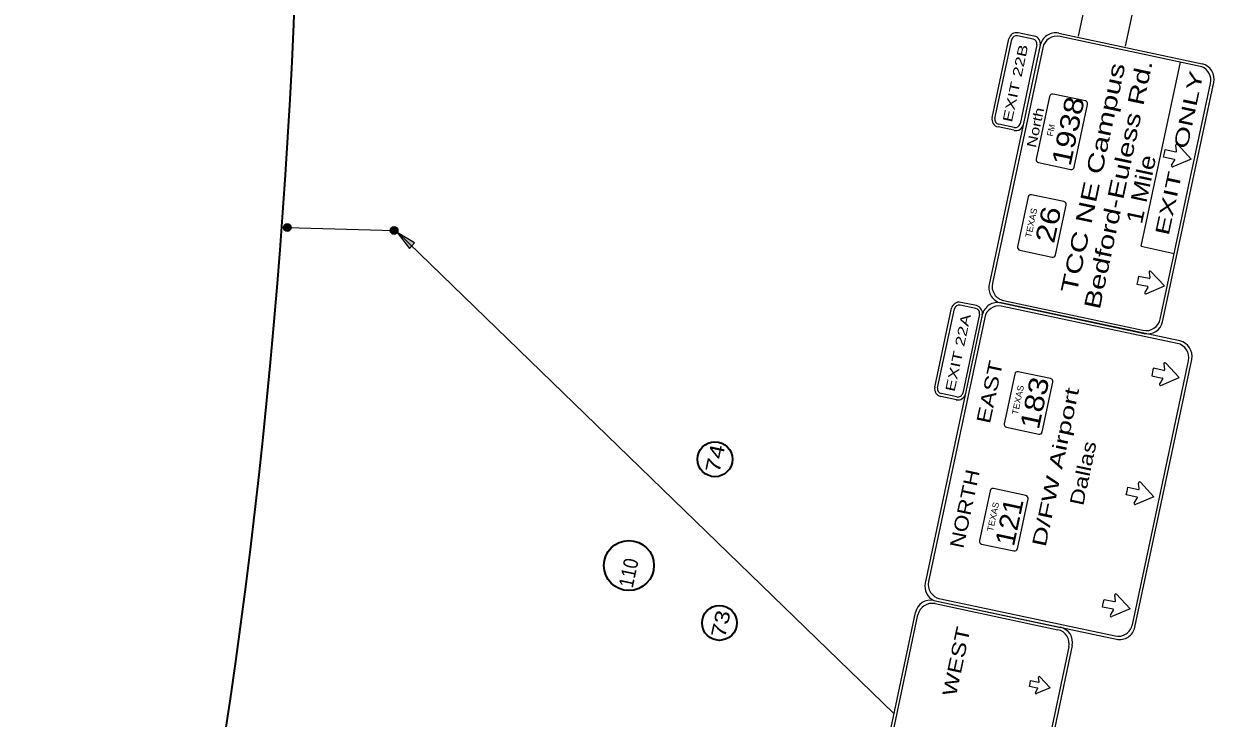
# Model space of a CAD drawing. Extents: x 2363411 to 2369702, y 6977197 to 6988655.
# Drawn here: x 2366110 to 2367261, y 6984077 to 6984748 of the extents above; entities that cross this region are included whole.
import ezdxf
from ezdxf.enums import TextEntityAlignment as Align

# ---------------------------------------------------------------- set-up
doc = ezdxf.new("R2010")
doc.units = 0
doc.header["$LTSCALE"] = 5.6
for name, color, linetype, lineweight in [('1', 7, 'Continuous', 25), ('17', 7, 'Continuous', 35), ('37', 7, 'Continuous', 13)]:
    doc.layers.add(name, color=color, linetype=linetype, lineweight=lineweight)

msp = doc.modelspace()

# ---------------------------------------------------------------- hatches: boundary and pattern name
at = {"layer": '1'}
for points in [[(2366366.647, 6984554.422, 1), (2366363.378, 6984547.712, 1)], [(2366469.912, 6984551.533, 1), (2366466.643, 6984544.824, 1)], [(2366471.082, 6984546.205), (2366483.256, 6984530.933), (2366487.97, 6984536.384)]]:
    msp.add_hatch(color=256, dxfattribs=at).paths.add_polyline_path(points)

# ---------------------------------------------------------------- linework, layer by layer
for p, q in [((2367138.659, 6984779.414), (2367129.448, 6984736.012)), ((2367184.046, 6984769.781), (2367174.834, 6984726.38)), ((2367085.868, 6984733.305), (2367070.751, 6984736.519)), ((2367086.453, 6984736.053), (2367071.337, 6984739.266)), ((2367110.621, 6984738.909), (2367249.302, 6984709.279)), ((2367248.837, 6984706.487), (2367111.875, 6984735.752)), ((2367092.767, 6984727.341), (2367043.331, 6984495.966)), ((2367046.219, 6984657.188), (2367062.442, 6984733.492)), ((2367095.133, 6984724.912), (2367046.484, 6984497.216)), ((2367048.968, 6984656.603), (2367065.189, 6984732.906)), ((2367089.48, 6984727.744), (2367073.249, 6984651.441)), ((2367190.312, 6984532.928), (2367228.339, 6984710.867)), ((2367208.74, 6984462.547), (2367257.429, 6984690.426)), ((2367211.039, 6984459.818), (2367260.475, 6984691.193)), ((2367101.799, 6984677.893), (2367088.902, 6984617.213)), ((2367136.372, 6984673.414), (2367105.14, 6984680.055)), ((2367125.636, 6984609.399), (2367138.533, 6984670.08)), ((2367067.103, 6984645.081), (2367051.995, 6984648.294)), ((2367067.69, 6984647.83), (2367052.579, 6984651.042)), ((2367213.604, 6984626.516), (2367223.763, 6984624.346)), ((2367224.582, 6984625.102), (2367223.811, 6984630.586)), ((2367091.065, 6984613.879), (2367122.296, 6984607.236)), ((2367219.688, 6984611.234), (2367222.623, 6984615.949)), ((2367081.118, 6984580.623), (2367070.876, 6984532.471)), ((2367115.69, 6984576.151), (2367084.459, 6984582.794)), ((2367107.61, 6984524.659), (2367117.852, 6984572.81)), ((2366365.012, 6984551.067), (2366468.277, 6984548.179)), ((2367073.047, 6984529.132), (2367104.277, 6984522.495)), ((2367190.312, 6984532.928), (2367222.317, 6984526.09)), ((2367197.915, 6984507.857), (2367198.686, 6984502.373)), ((2367186.131, 6984496.397), (2367196.293, 6984494.229)), ((2367196.727, 6984493.22), (2367193.792, 6984488.505)), ((2366990.767, 6984396.652), (2367006.998, 6984472.948)), ((2366993.515, 6984396.066), (2367009.737, 6984472.369)), ((2367030.417, 6984472.755), (2367015.307, 6984475.967)), ((2367031.004, 6984475.509), (2367015.893, 6984478.722)), ((2367227.663, 6984441.357), (2367054.898, 6984478.099)), ((2367054.898, 6984478.099), (2367193.245, 6984448.546)), ((2367225.242, 6984438.994), (2367055.105, 6984475.166)), ((2367057.334, 6984480.469), (2367191.995, 6984451.698)), ((2367036.777, 6984466.612), (2366981.625, 6984207.244)), ((2367039.139, 6984464.209), (2366984.841, 6984208.865)), ((2367034.021, 6984467.2), (2367017.798, 6984390.896)), ((2367181.781, 6984166.964), (2367236.077, 6984422.314)), ((2367184.143, 6984164.544), (2367239.219, 6984423.555)), ((2367212.21, 6984412.935), (2367212.186, 6984412.928)), ((2367212.236, 6984419.177), (2367213.003, 6984413.701)), ((2367068.229, 6984409.399), (2367057.993, 6984361.247)), ((2367102.8, 6984404.927), (2367071.57, 6984411.569)), ((2367094.729, 6984353.434), (2367104.963, 6984401.586)), ((2367211.055, 6984404.528), (2367208.123, 6984399.82)), ((2367012.246, 6984387.278), (2366997.128, 6984390.498)), ((2367011.66, 6984384.538), (2366996.55, 6984387.75)), ((2367060.156, 6984357.907), (2367091.387, 6984351.264)), ((2367078.783, 6984291.969), (2367047.551, 6984298.612)), ((2367177.528, 6984299.87), (2367187.689, 6984297.703)), ((2367188.499, 6984298.473), (2367187.734, 6984303.95)), ((2367044.212, 6984296.441), (2367033.969, 6984248.29)), ((2367070.704, 6984240.476), (2367080.946, 6984288.627)), ((2367183.619, 6984284.601), (2367186.551, 6984289.308)), ((2367036.139, 6984244.949), (2367067.369, 6984238.313)), ((2367165.459, 6984190.121), (2367164.693, 6984195.597)), ((2366990.007, 6984190.505), (2367166.348, 6984153.003)), ((2366990.007, 6984190.505), (2367112.427, 6984164.467)), ((2366991.262, 6984187.372), (2367109.633, 6984162.194)), ((2366996.484, 6984191.993), (2367165.099, 6984156.143)), ((2367154.487, 6984191.517), (2367164.649, 6984189.35)), ((2366937.872, 6984017.444), (2366972.227, 6984178.958)), ((2366941.013, 6984018.692), (2366974.591, 6984176.538)), ((2367160.579, 6984176.248), (2367163.511, 6984180.955)), ((2367120.468, 6984145.521), (2367086.899, 6983987.669)), ((2367123.601, 6984146.769), (2367089.253, 6983985.25)), ((2367091.704, 6984111.924), (2367091.125, 6984116.022)), ((2367083.481, 6984112.961), (2367091.093, 6984111.353)), ((2367088.043, 6984101.516), (2367090.234, 6984105.051))]:
    msp.add_line(p, q, dxfattribs=at)
at = {"layer": '1', "lineweight": 13}
msp.add_line((2366951.401, 6984081.046), (2366471.632, 6984546.544), dxfattribs=at)
at = {"layer": '1'}
for points in [[(2367225.591, 6984631.376), (2367238.622, 6984617.302), (2367220.991, 6984609.794)], [(2367222.189, 6984616.958), (2367212.027, 6984619.126), (2367212.822, 6984622.817), (2367213.604, 6984626.516)], [(2367195.095, 6984487.065), (2367212.726, 6984494.573), (2367199.695, 6984508.647)], [(2367197.867, 6984501.617), (2367187.708, 6984503.787), (2367186.926, 6984500.088), (2367186.131, 6984496.397)], [(2367212.186, 6984412.928), (2367202.024, 6984415.088), (2367201.241, 6984411.389), (2367200.457, 6984407.698), (2367210.619, 6984405.538)], [(2367209.428, 6984398.38), (2367227.053, 6984405.898), (2367214.016, 6984419.96)], [(2367186.114, 6984290.319), (2367175.953, 6984292.478), (2367176.744, 6984296.17), (2367177.528, 6984299.87)], [(2367189.512, 6984304.742), (2367202.549, 6984290.68), (2367184.923, 6984283.154)], [(2367166.471, 6984196.388), (2367179.508, 6984182.327), (2367161.883, 6984174.802)], [(2367163.074, 6984181.966), (2367152.913, 6984184.126), (2367153.703, 6984187.817), (2367154.487, 6984191.517)], [(2367092.451, 6984116.614), (2367102.224, 6984106.083), (2367089.01, 6984100.431)], [(2367089.911, 6984105.805), (2367082.29, 6984107.42), (2367082.883, 6984110.191), (2367083.481, 6984112.961)]]:
    msp.add_lwpolyline(points, dxfattribs=at)
msp.add_lwpolyline([(2366471.082, 6984546.205), (2366483.256, 6984530.933), (2366487.97, 6984536.384)], close=True, dxfattribs=at)
for centre in [(2366365.012, 6984551.067), (2366468.278, 6984548.179)]:
    msp.add_circle(centre, 3.732, dxfattribs=at)
at = {"layer": '1', "lineweight": 35}
msp.add_arc((2359877.328, 6985028.058), 6500, 337.9611, 358.49155, dxfattribs=at)
at = {"layer": '1'}
for centre, radius, start, end in [((2367069.779, 6984731.93), 7.501, 77.99433, 167.99433), ((2367069.779, 6984731.93), 4.688, 77.99433, 167.99433), ((2367085.43, 6984728.901), 7.501, 347.99433, 77.99433), ((2367107.483, 6984724.196), 15.049, 77.93925, 169.35675), ((2367108.929, 6984721.964), 14.108, 77.93925, 167.93925), ((2367084.892, 6984728.716), 4.688, 347.99433, 77.99433), ((2367243.631, 6984693.374), 14.108, 347.93925, 68.3439), ((2367245.824, 6984694.637), 15.049, 346.76968, 76.63979), ((2367104.551, 6984677.305), 2.813, 77.99516, 167.99516), ((2367135.785, 6984670.663), 2.813, 347.99516, 77.99516), ((2367053.553, 6984655.63), 7.501, 167.99433, 257.99433), ((2367053.553, 6984655.63), 4.688, 167.99433, 257.99433), ((2367069.135, 6984652.316), 7.501, 257.99433, 347.99433), ((2367068.666, 6984652.416), 4.688, 257.99433, 347.99433), ((2367224.831, 6984630.715), 1.012, 42.67771, 188.05885), ((2367223.928, 6984625.009), 0.675, 257.93922, 7.92232), ((2367091.646, 6984616.629), 2.813, 167.99516, 257.99516), ((2367122.88, 6984609.987), 2.813, 257.99516, 347.99516), ((2367220.558, 6984610.718), 1.012, 147.81958, 293.20072), ((2367222.066, 6984616.295), 0.675, 327.95611, 77.93922), ((2367083.867, 6984580.044), 2.813, 77.99516, 167.99516), ((2367115.102, 6984573.402), 2.813, 347.99516, 77.99516), ((2367073.626, 6984531.881), 2.813, 167.99516, 257.99516), ((2367104.86, 6984525.24), 2.813, 257.99516, 347.99516), ((2367198.936, 6984507.986), 1.012, 42.67771, 188.05885), ((2367058.047, 6984492.821), 15.049, 167.93925, 257.93925), ((2367060.28, 6984494.268), 14.108, 167.93925, 257.93925), ((2367196.171, 6984493.566), 0.675, 327.95611, 77.93922), ((2367198.033, 6984502.28), 0.675, 257.93922, 7.92232), ((2367194.663, 6984487.989), 1.012, 147.81958, 293.20072), ((2367014.327, 6984471.386), 7.501, 77.99516, 167.99516), ((2367014.327, 6984471.386), 4.688, 77.99516, 167.99516), ((2367029.44, 6984468.172), 4.688, 347.99516, 77.99516), ((2367029.44, 6984468.172), 7.501, 347.99516, 77.99516), ((2367051.448, 6984463.497), 15.001, 76.71396, 167.99516), ((2367052.894, 6984461.281), 14.063, 80.95422, 167.99516), ((2367194.942, 6984465.495), 14.108, 257.93925, 347.93925), ((2367196.389, 6984463.262), 15.049, 257.93925, 346.76968), ((2367222.32, 6984425.231), 14.063, 347.99516, 77.99516), ((2367224.544, 6984426.675), 15.001, 347.99516, 77.99516), ((2367212.35, 6984413.595), 0.675, 257.99516, 7.97826), ((2367213.248, 6984419.302), 1.012, 42.73365, 188.11479), ((2367070.98, 6984408.819), 2.813, 77.99516, 167.99516), ((2367102.215, 6984402.177), 2.813, 347.99516, 77.99516), ((2367210.497, 6984404.879), 0.675, 328.01205, 77.99516), ((2366998.102, 6984395.085), 7.501, 167.99516, 257.99516), ((2366998.102, 6984395.085), 4.688, 167.99516, 257.99516), ((2367013.215, 6984391.871), 7.501, 257.99516, 347.99516), ((2367013.215, 6984391.871), 4.688, 257.99516, 347.99516), ((2367208.995, 6984399.301), 1.012, 147.87552, 293.25666), ((2367060.739, 6984360.656), 2.813, 167.99516, 257.99516), ((2367091.973, 6984354.015), 2.813, 257.99516, 347.99516), ((2367046.961, 6984295.862), 2.813, 77.99516, 167.99516), ((2367187.849, 6984298.374), 0.675, 257.99516, 7.97826), ((2367188.746, 6984304.081), 1.012, 42.73365, 188.11479), ((2367078.195, 6984289.22), 2.813, 347.99516, 77.99516), ((2367185.996, 6984289.658), 0.675, 328.01205, 77.99516), ((2367184.493, 6984284.08), 1.012, 147.87552, 293.25666), ((2367036.719, 6984247.699), 2.813, 167.99516, 257.99516), ((2367067.953, 6984241.058), 2.813, 257.99516, 347.99516), ((2366996.293, 6984204.122), 15.001, 167.99516, 245.22121), ((2366998.595, 6984205.933), 14.063, 167.99516, 257.99516), ((2367165.706, 6984195.728), 1.012, 42.73365, 188.11479), ((2366986.896, 6984175.838), 15.001, 77.99525, 167.99525), ((2366988.34, 6984173.614), 14.063, 77.99525, 167.99525), ((2367164.808, 6984190.021), 0.675, 257.99516, 7.97826), ((2367161.453, 6984175.727), 1.012, 147.87552, 293.25666), ((2367162.955, 6984181.305), 0.675, 328.01205, 77.99516), ((2367106.712, 6984148.443), 14.063, 347.99525, 77.99525), ((2367108.936, 6984149.888), 15.001, 347.99525, 77.99525), ((2367168.023, 6984169.891), 14.063, 257.99516, 347.99516), ((2367169.467, 6984167.667), 15.001, 257.99516, 347.99516), ((2367091.883, 6984116.124), 0.759, 42.73196, 188.11309), ((2367089.82, 6984105.307), 0.506, 328.01036, 77.99346), ((2367091.21, 6984111.843), 0.506, 257.99346, 7.97657), ((2367088.693, 6984101.123), 0.759, 147.87383, 293.25497)]:
    msp.add_arc(centre, radius, start, end, dxfattribs=at)
at = {"layer": '17'}
for centre, radius in [((2366778.372, 6984326.964), 16.828), ((2366695.25, 6984224.179), 24.19), ((2366782.677, 6984168.728), 16.828)]:
    msp.add_circle(centre, radius, dxfattribs=at)
at = {"layer": '37'}
msp.add_line((2367088.416, 6984660.876), (2367087.523, 6984659.087), dxfattribs=at)

# ---------------------------------------------------------------- texts
at = {"layer": '1'}
for s, height, rotation, width, p in [('EXIT 22B', 9.188, 77.994, 1.45, (2367073.24, 6984689.621)), ('TCC NE Campus', 15.68, 77.939, 1.4, (2367151.437, 6984597.449)), ('Bedford-Euless Rd.', 15.68, 77.939, 1.35, (2367175.843, 6984591.161)), ('EXIT   ONLY', 13.5, 77.939, 1.55, (2367233.743, 6984621.698)), ('North', 9.188, 77.994, 1.3, (2367092.566, 6984646.777)), ('1 Mile', 15.68, 77.939, 1.2, (2367197.929, 6984586.441)), ('EXIT 22A', 9.188, 77.995, 1.45, (2367017.786, 6984429.083)), ('EAST', 13.5, 77.995, 1.3, (2367050.45, 6984390.673)), ('D/FW Airport', 13.5, 77.995, 1.5, (2367114.122, 6984318.045)), ('Dallas', 13.5, 77.995, 1.25, (2367140.761, 6984312.101)), ('NORTH', 13.5, 77.995, 1.2, (2367026.42, 6984277.709)), ('WEST', 13.5, 77.995, 1.3, (2367018.314, 6984130.096))]:
    msp.add_text(s, height=height, rotation=rotation, dxfattribs=dict(at, width=width)).set_placement(p, align=Align.CENTER)
for s, height, width, p in [('1938', 18.75, 1.2, (2367121.899, 6984609.67)), ('TEXAS', 6, 1.1, (2367083.99, 6984540.763)), ('26', 18.75, 1.25, (2367106, 6984534.893)), ('183', 18.75, 1.2, (2367091.244, 6984354.877)), ('TEXAS', 6, 1.1, (2367071.101, 6984369.537)), ('121', 18.75, 1.1, (2367067.227, 6984241.92)), ('TEXAS', 6, 1.1, (2367047.084, 6984256.58))]:
    msp.add_text(s, height=height, rotation=77.995, dxfattribs=dict(at, width=width)).set_placement(p)
msp.add_text('FM', height=6, rotation=77.995, dxfattribs=at).set_placement((2367104.835, 6984638.802))
at = {"layer": '17'}
for s, width, p in [('74', 1.3, (2366785.394, 6984326.32)), ('110', 0.9, (2366701.777, 6984215.707)), ('73', 1.25, (2366790.796, 6984166.388))]:
    msp.add_text(s, height=14, rotation=77.939, dxfattribs=dict(at, width=width)).set_placement(p, align=Align.CENTER)

doc.saveas('drawing.dxf')
